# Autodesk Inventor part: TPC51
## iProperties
Shininess: 64.0
Length Units: 11272
Angle Units: 11279
Time Units: 11290
Mass Units: 11286
Length Display Precision: 3
Angle Display Precision: 2
Compacted: True
Part Number: TPC51
Document SubType Name: Modeling
Created: 2004-08
Designer: Lori
Manufacturer: Standard
Standards Organization: Custom
Density: 0.0
Volumn: 0.0
Area: 0.0
PropertySet Name: Model Information
Control State: 0
Master: False
Checked Out: False
Author: Lori
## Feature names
1. Base1
